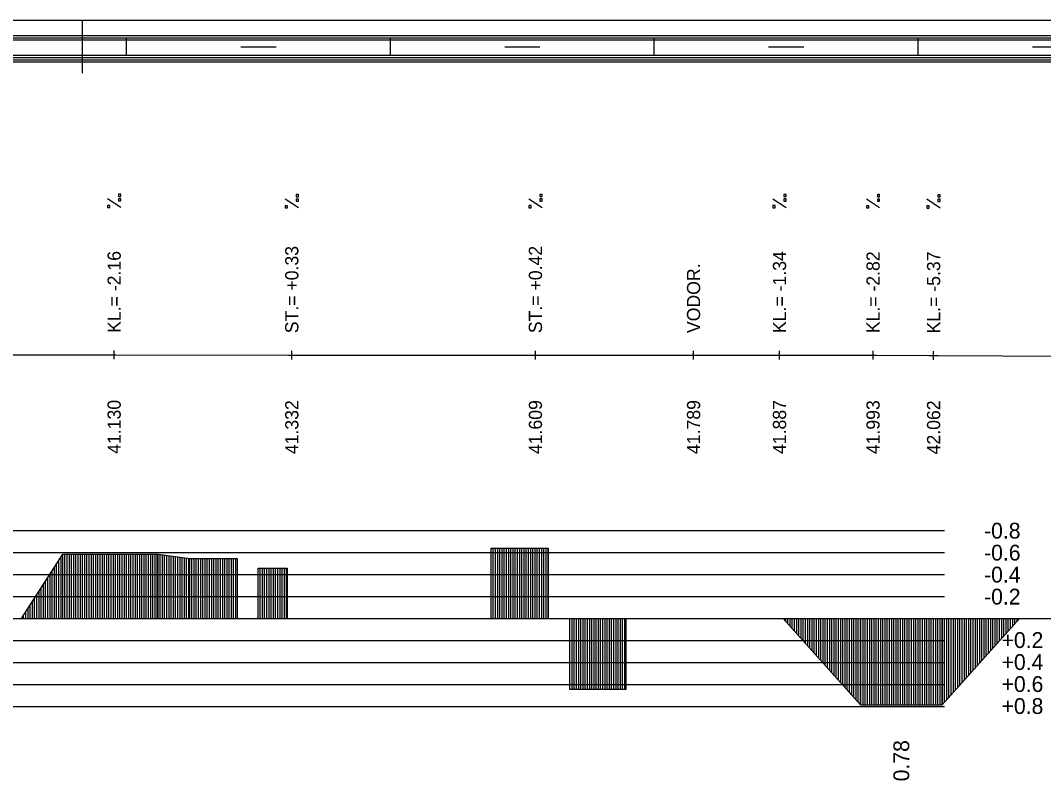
# Model space of a CAD drawing. Extents: x 2 to 10148, y 0 to 380.
# Drawn here: x 4402.9 to 4519.3, y 293.6 to 380 of the extents above; entities that cross this region are included whole.
import ezdxf

# ---------------------------------------------------------------- set-up
doc = ezdxf.new("R2010")
doc.units = 0
for name, color, linetype in [('NIVELETA_CARA', 7, 'Continuous'), ('NIVELETA_TEXT', 7, 'Continuous'), ('RAM', 7, 'Continuous'), ('ZRYCHL_CARA_C', 7, 'Continuous'), ('ZRYCHL_RASTR', 7, 'Continuous'), ('ZRYCHL_TEXT', 7, 'Continuous')]:
    doc.layers.add(name, color=color, linetype=linetype)

msp = doc.modelspace()

# ---------------------------------------------------------------- linework, layer by layer
at = {"layer": 'NIVELETA_CARA'}
for p, q in [((4386.25, 342.02), (4413.39, 341.98)), ((4413.59, 341.48), (4413.59, 342.48)), ((4433.79, 341.44), (4433.79, 342.44)), ((4461.49, 341.45), (4461.49, 342.45)), ((4479.47, 341.46), (4479.47, 342.46)), ((4489.24, 341.46), (4489.24, 342.46)), ((4499.88, 341.44), (4499.88, 342.44)), ((4506.76, 341.42), (4506.76, 342.42)), ((4413.39, 341.98), (4413.59, 341.98)), ((4413.59, 341.98), (4413.8, 341.98)), ((4413.8, 341.98), (4433.42, 341.94)), ((4433.42, 341.94), (4433.79, 341.94)), ((4433.79, 341.94), (4434.17, 341.94)), ((4434.17, 341.94), (4461.47, 341.95)), ((4461.47, 341.95), (4461.49, 341.95)), ((4461.49, 341.95), (4461.51, 341.95)), ((4461.51, 341.95), (4479.36, 341.96)), ((4479.36, 341.96), (4479.47, 341.96)), ((4479.47, 341.96), (4479.57, 341.96)), ((4479.57, 341.96), (4489.04, 341.96)), ((4489.04, 341.96), (4489.24, 341.96)), ((4489.24, 341.96), (4489.44, 341.96)), ((4489.44, 341.96), (4499.51, 341.94)), ((4499.51, 341.94), (4499.88, 341.94)), ((4499.88, 341.94), (4500.25, 341.94)), ((4500.25, 341.94), (4506.25, 341.93)), ((4506.25, 341.93), (4506.76, 341.92)), ((4506.76, 341.92), (4507.27, 341.92)), ((4507.27, 341.92), (4524.9, 341.83))]:
    msp.add_line(p, q, dxfattribs=at)
at = {"layer": 'NIVELETA_TEXT'}
for p, q in [((4414.34, 358.74), (4412.85, 359.73)), ((4414.34, 360.25), (4414.09, 360.25)), ((4414.09, 360.25), (4414.09, 360.01)), ((4414.09, 360.01), (4414.1, 360)), ((4414.09, 360), (4414.34, 360)), ((4414.34, 359.74), (4414.09, 359.74)), ((4414.09, 359.74), (4414.09, 359.5)), ((4414.09, 359.5), (4414.1, 359.49)), ((4414.09, 359.49), (4414.34, 359.49)), ((4414.34, 360), (4414.34, 360.25)), ((4414.34, 359.49), (4414.34, 359.74)), ((4434.54, 358.69), (4433.04, 359.68)), ((4434.54, 360.21), (4434.29, 360.21)), ((4434.29, 360.21), (4434.29, 359.97)), ((4434.29, 359.97), (4434.3, 359.96)), ((4434.29, 359.96), (4434.54, 359.96)), ((4434.54, 359.7), (4434.29, 359.7)), ((4434.29, 359.7), (4434.29, 359.45)), ((4434.29, 359.45), (4434.54, 359.45)), ((4434.29, 359.45), (4434.3, 359.45)), ((4434.54, 359.96), (4434.54, 360.21)), ((4434.54, 359.45), (4434.54, 359.7)), ((4462.24, 358.7), (4460.74, 359.69)), ((4462.24, 360.22), (4461.99, 360.22)), ((4461.99, 360.22), (4461.99, 359.98)), ((4461.99, 359.98), (4462, 359.97)), ((4461.99, 359.97), (4462.24, 359.97)), ((4462.24, 359.71), (4461.99, 359.71)), ((4461.99, 359.71), (4461.99, 359.46)), ((4461.99, 359.46), (4462.24, 359.46)), ((4461.99, 359.46), (4462, 359.46)), ((4462.24, 359.97), (4462.24, 360.22)), ((4462.24, 359.46), (4462.24, 359.71)), ((4489.99, 358.71), (4488.49, 359.7)), ((4489.99, 360.23), (4489.74, 360.23)), ((4489.74, 360.23), (4489.74, 359.98)), ((4489.74, 359.98), (4489.99, 359.98)), ((4489.74, 359.98), (4489.75, 359.98)), ((4489.99, 359.71), (4489.74, 359.71)), ((4489.74, 359.71), (4489.74, 359.47)), ((4489.74, 359.47), (4489.99, 359.47)), ((4489.74, 359.47), (4489.75, 359.47)), ((4489.99, 359.98), (4489.99, 360.23)), ((4489.99, 359.47), (4489.99, 359.71)), ((4500.63, 358.7), (4499.14, 359.69)), ((4500.63, 360.21), (4500.38, 360.21)), ((4500.38, 360.21), (4500.38, 359.97)), ((4500.38, 359.97), (4500.39, 359.96)), ((4500.38, 359.96), (4500.63, 359.96)), ((4500.63, 359.7), (4500.38, 359.7)), ((4500.38, 359.7), (4500.38, 359.46)), ((4500.38, 359.46), (4500.39, 359.45)), ((4500.38, 359.45), (4500.63, 359.45)), ((4500.63, 359.96), (4500.63, 360.21)), ((4500.63, 359.45), (4500.63, 359.7)), ((4507.51, 358.68), (4506.01, 359.67)), ((4507.51, 360.19), (4507.26, 360.19)), ((4507.26, 360.19), (4507.26, 359.95)), ((4507.26, 359.95), (4507.27, 359.94)), ((4507.26, 359.94), (4507.51, 359.94)), ((4507.51, 359.68), (4507.26, 359.68)), ((4507.26, 359.68), (4507.26, 359.44)), ((4507.51, 359.94), (4507.51, 360.19)), ((4507.51, 359.43), (4507.51, 359.68)), ((4413.09, 358.98), (4412.85, 358.98)), ((4412.85, 358.98), (4412.85, 358.74)), ((4412.85, 358.74), (4413.09, 358.74)), ((4412.85, 358.74), (4412.85, 358.74)), ((4413.09, 358.74), (4413.09, 358.98)), ((4433.29, 358.94), (4433.04, 358.94)), ((4433.04, 358.94), (4433.04, 358.7)), ((4433.04, 358.7), (4433.05, 358.69)), ((4433.04, 358.69), (4433.29, 358.69)), ((4433.29, 358.69), (4433.29, 358.94)), ((4460.99, 358.95), (4460.74, 358.95)), ((4460.74, 358.95), (4460.74, 358.71)), ((4460.74, 358.71), (4460.75, 358.7)), ((4460.74, 358.7), (4460.99, 358.7)), ((4460.99, 358.7), (4460.99, 358.95)), ((4488.74, 358.96), (4488.49, 358.96)), ((4488.49, 358.96), (4488.49, 358.71)), ((4488.49, 358.71), (4488.74, 358.71)), ((4488.49, 358.71), (4488.5, 358.71)), ((4488.74, 358.71), (4488.74, 358.96)), ((4499.38, 358.94), (4499.14, 358.94)), ((4499.14, 358.94), (4499.14, 358.7)), ((4499.14, 358.7), (4499.38, 358.7)), ((4499.14, 358.7), (4499.14, 358.7)), ((4499.38, 358.7), (4499.38, 358.94)), ((4506.26, 358.92), (4506.01, 358.92)), ((4506.01, 358.92), (4506.01, 358.68)), ((4506.01, 358.68), (4506.26, 358.68)), ((4506.01, 358.68), (4506.02, 358.68)), ((4506.26, 358.68), (4506.26, 358.92)), ((4507.26, 359.44), (4507.27, 359.43)), ((4507.26, 359.43), (4507.51, 359.43))]:
    msp.add_line(p, q, dxfattribs=at)
at = {"layer": 'RAM'}
for p, q in [((5128.6, 380), (4045.76, 380)), ((4410, 374), (4410, 380)), ((5128.6, 378.25), (4045.76, 378.25)), ((5128.6, 378), (4045.76, 378)), ((5128.6, 377.75), (4045.76, 377.75)), ((4415, 376), (4415, 378)), ((4428, 377), (4432, 377)), ((4445, 376), (4445, 378)), ((4458, 377), (4462, 377)), ((4475, 376), (4475, 378)), ((4488, 377), (4492, 377)), ((4505, 376), (4505, 378)), ((4518, 377), (4522, 377)), ((5128.6, 376), (4045.76, 376)), ((5128.6, 375.75), (4045.76, 375.75)), ((5128.6, 375.5), (4045.76, 375.5)), ((5128.6, 375.25), (4045.76, 375.25))]:
    msp.add_line(p, q, dxfattribs=at)
at = {"layer": 'ZRYCHL_CARA_C'}
for p, q in [((4456.45, 312), (4456.45, 320.01)), ((4456.45, 312), (4456.45, 320.01)), ((4456.45, 320.01), (4462.95, 320.01)), ((4456.7, 312), (4456.7, 320.01)), ((4456.95, 312), (4456.95, 320.01)), ((4457.2, 312), (4457.2, 320.01)), ((4457.45, 312), (4457.45, 320.01)), ((4457.7, 312), (4457.7, 320.01)), ((4457.95, 312), (4457.95, 320.01)), ((4458.2, 312), (4458.2, 320.01)), ((4458.45, 312), (4458.45, 320.01)), ((4458.7, 312), (4458.7, 320.01)), ((4458.95, 312), (4458.95, 320.01)), ((4459.2, 312), (4459.2, 320.01)), ((4459.45, 312), (4459.45, 320.01)), ((4459.7, 312), (4459.7, 320.01)), ((4459.95, 312), (4459.95, 320.01)), ((4460.2, 312), (4460.2, 320.01)), ((4460.45, 312), (4460.45, 320.01)), ((4460.7, 312), (4460.7, 320.01)), ((4460.95, 312), (4460.95, 320.01)), ((4461.2, 312), (4461.2, 320.01)), ((4461.45, 312), (4461.45, 320.01)), ((4461.7, 312), (4461.7, 320.01)), ((4461.95, 312), (4461.95, 320.01)), ((4462.2, 312), (4462.2, 320.01)), ((4462.45, 312), (4462.45, 320.01)), ((4462.7, 312), (4462.7, 320.01)), ((4462.95, 312), (4462.95, 320.01)), ((4462.95, 320.01), (4462.95, 312)), ((4403.05, 312), (4407.75, 319.32)), ((4407.55, 312), (4407.55, 319.01)), ((4407.75, 312), (4407.75, 319.32)), ((4407.75, 319.32), (4418.58, 319.32)), ((4408, 312), (4408, 319.32)), ((4408.25, 312), (4408.25, 319.32)), ((4408.5, 312), (4408.5, 319.32)), ((4408.75, 312), (4408.75, 319.32)), ((4409, 312), (4409, 319.32)), ((4409.25, 312), (4409.25, 319.32)), ((4409.5, 312), (4409.5, 319.32)), ((4409.75, 312), (4409.75, 319.32)), ((4410, 312), (4410, 319.32)), ((4410.25, 312), (4410.25, 319.32)), ((4410.5, 312), (4410.5, 319.32)), ((4410.75, 312), (4410.75, 319.32)), ((4411, 312), (4411, 319.32)), ((4411.25, 312), (4411.25, 319.32)), ((4411.5, 312), (4411.5, 319.32)), ((4411.75, 312), (4411.75, 319.32)), ((4412, 312), (4412, 319.32)), ((4412.25, 312), (4412.25, 319.32)), ((4412.5, 312), (4412.5, 319.32)), ((4412.75, 312), (4412.75, 319.32)), ((4413, 312), (4413, 319.32)), ((4413.25, 312), (4413.25, 319.32)), ((4413.5, 312), (4413.5, 319.32)), ((4413.75, 312), (4413.75, 319.32)), ((4414, 312), (4414, 319.32)), ((4414.25, 312), (4414.25, 319.32)), ((4414.5, 312), (4414.5, 319.32)), ((4414.75, 312), (4414.75, 319.32)), ((4415, 312), (4415, 319.32)), ((4415.25, 312), (4415.25, 319.32)), ((4415.5, 312), (4415.5, 319.32)), ((4415.75, 312), (4415.75, 319.32)), ((4416, 312), (4416, 319.32)), ((4416.25, 312), (4416.25, 319.32)), ((4416.5, 312), (4416.5, 319.32)), ((4416.75, 312), (4416.75, 319.32)), ((4417, 312), (4417, 319.32)), ((4417.25, 312), (4417.25, 319.32)), ((4417.5, 312), (4417.5, 319.32)), ((4417.75, 312), (4417.75, 319.32)), ((4418, 312), (4418, 319.32)), ((4418.25, 312), (4418.25, 319.32)), ((4418.5, 312), (4418.5, 319.32)), ((4418.58, 312), (4418.58, 319.32)), ((4418.58, 319.32), (4422.18, 318.84)), ((4418.83, 312), (4418.83, 319.29)), ((4419.08, 312), (4419.08, 319.26)), ((4419.33, 312), (4419.33, 319.22)), ((4419.58, 312), (4419.58, 319.19)), ((4419.83, 312), (4419.83, 319.16)), ((4420.08, 312), (4420.08, 319.12)), ((4420.33, 312), (4420.33, 319.09)), ((4420.58, 312), (4420.58, 319.05)), ((4420.83, 312), (4420.83, 319.02)), ((4421.08, 312), (4421.08, 318.99)), ((4421.33, 312), (4421.33, 318.95)), ((4421.58, 312), (4421.58, 318.92)), ((4421.83, 312), (4421.83, 318.88)), ((4422.08, 312), (4422.08, 318.85)), ((4422.18, 312), (4422.18, 318.84)), ((4422.18, 318.84), (4427.56, 318.84)), ((4422.43, 312), (4422.43, 318.84)), ((4422.68, 312), (4422.68, 318.84)), ((4422.93, 312), (4422.93, 318.84)), ((4423.18, 312), (4423.18, 318.84)), ((4423.43, 312), (4423.43, 318.84)), ((4423.68, 312), (4423.68, 318.84)), ((4423.93, 312), (4423.93, 318.84)), ((4424.18, 312), (4424.18, 318.84)), ((4424.43, 312), (4424.43, 318.84)), ((4424.68, 312), (4424.68, 318.84)), ((4424.93, 312), (4424.93, 318.84)), ((4425.18, 312), (4425.18, 318.84)), ((4425.43, 312), (4425.43, 318.84)), ((4425.68, 312), (4425.68, 318.84)), ((4425.93, 312), (4425.93, 318.84)), ((4426.18, 312), (4426.18, 318.84)), ((4426.43, 312), (4426.43, 318.84)), ((4426.68, 312), (4426.68, 318.84)), ((4426.93, 312), (4426.93, 318.84)), ((4427.18, 312), (4427.18, 318.84)), ((4427.43, 312), (4427.43, 318.84)), ((4427.56, 318.84), (4427.56, 312)), ((4406.8, 312), (4406.8, 317.84)), ((4407.05, 312), (4407.05, 318.23)), ((4407.3, 312), (4407.3, 318.62)), ((4429.95, 312), (4429.95, 317.73)), ((4429.95, 312), (4429.95, 317.73)), ((4429.95, 317.73), (4433.27, 317.73)), ((4430.2, 312), (4430.2, 317.73)), ((4430.45, 312), (4430.45, 317.73)), ((4430.7, 312), (4430.7, 317.73)), ((4430.95, 312), (4430.95, 317.73)), ((4431.2, 312), (4431.2, 317.73)), ((4431.45, 312), (4431.45, 317.73)), ((4431.7, 312), (4431.7, 317.73)), ((4431.95, 312), (4431.95, 317.73)), ((4432.2, 312), (4432.2, 317.73)), ((4432.45, 312), (4432.45, 317.73)), ((4432.7, 312), (4432.7, 317.73)), ((4432.95, 312), (4432.95, 317.73)), ((4433.2, 312), (4433.2, 317.73)), ((4433.27, 317.73), (4433.27, 312)), ((4406.05, 312), (4406.05, 316.67)), ((4406.3, 312), (4406.3, 317.06)), ((4406.55, 312), (4406.55, 317.45)), ((4405.3, 312), (4405.3, 315.51)), ((4405.55, 312), (4405.55, 315.9)), ((4405.8, 312), (4405.8, 316.29)), ((4404.55, 312), (4404.55, 314.34)), ((4404.8, 312), (4404.8, 314.73)), ((4405.05, 312), (4405.05, 315.12)), ((4403.8, 312), (4403.8, 313.17)), ((4404.05, 312), (4404.05, 313.56)), ((4404.3, 312), (4404.3, 313.95)), ((4045.76, 312), (5128.6, 312)), ((4403.3, 312), (4403.3, 312.39)), ((4403.55, 312), (4403.55, 312.78)), ((4465.37, 312), (4465.37, 303.99)), ((4465.37, 312), (4465.37, 303.99)), ((4465.62, 312), (4465.62, 303.99)), ((4465.87, 312), (4465.87, 303.99)), ((4466.12, 312), (4466.12, 303.99)), ((4466.37, 312), (4466.37, 303.99)), ((4466.62, 312), (4466.62, 303.99)), ((4466.87, 312), (4466.87, 303.99)), ((4467.12, 312), (4467.12, 303.99)), ((4467.37, 312), (4467.37, 303.99)), ((4467.62, 312), (4467.62, 303.99)), ((4467.87, 312), (4467.87, 303.99)), ((4468.12, 312), (4468.12, 303.99)), ((4468.37, 312), (4468.37, 303.99)), ((4468.62, 312), (4468.62, 303.99)), ((4468.87, 312), (4468.87, 303.99)), ((4469.12, 312), (4469.12, 303.99)), ((4469.37, 312), (4469.37, 303.99)), ((4469.62, 312), (4469.62, 303.99)), ((4469.87, 312), (4469.87, 303.99)), ((4470.12, 312), (4470.12, 303.99)), ((4470.37, 312), (4470.37, 303.99)), ((4470.62, 312), (4470.62, 303.99)), ((4470.87, 312), (4470.87, 303.99)), ((4471.12, 312), (4471.12, 303.99)), ((4471.37, 312), (4471.37, 303.99)), ((4471.62, 312), (4471.62, 303.99)), ((4471.8, 303.99), (4471.8, 312)), ((4489.66, 312), (4498.46, 302.2)), ((4489.91, 312), (4489.91, 311.72)), ((4490.16, 312), (4490.16, 311.44)), ((4490.41, 312), (4490.41, 311.16)), ((4490.66, 312), (4490.66, 310.89)), ((4490.91, 312), (4490.91, 310.61)), ((4491.16, 312), (4491.16, 310.33)), ((4491.41, 312), (4491.41, 310.05)), ((4491.66, 312), (4491.66, 309.77)), ((4491.91, 312), (4491.91, 309.49)), ((4492.16, 312), (4492.16, 309.22)), ((4492.41, 312), (4492.41, 308.94)), ((4492.66, 312), (4492.66, 308.66)), ((4492.91, 312), (4492.91, 308.38)), ((4493.16, 312), (4493.16, 308.1)), ((4493.41, 312), (4493.41, 307.82)), ((4493.66, 312), (4493.66, 307.54)), ((4493.91, 312), (4493.91, 307.27)), ((4494.16, 312), (4494.16, 306.99)), ((4494.41, 312), (4494.41, 306.71)), ((4494.66, 312), (4494.66, 306.43)), ((4494.91, 312), (4494.91, 306.15)), ((4495.16, 312), (4495.16, 305.87)), ((4495.41, 312), (4495.41, 305.59)), ((4495.66, 312), (4495.66, 305.32)), ((4495.91, 312), (4495.91, 305.04)), ((4496.16, 312), (4496.16, 304.76)), ((4496.41, 312), (4496.41, 304.48)), ((4496.66, 312), (4496.66, 304.2)), ((4496.91, 312), (4496.91, 303.92)), ((4497.16, 312), (4497.16, 303.65)), ((4497.41, 312), (4497.41, 303.37)), ((4497.66, 312), (4497.66, 303.09)), ((4497.91, 312), (4497.91, 302.81)), ((4498.16, 312), (4498.16, 302.53)), ((4498.41, 312), (4498.41, 302.25)), ((4498.46, 312), (4498.46, 302.2)), ((4498.71, 312), (4498.71, 302.2)), ((4498.96, 312), (4498.96, 302.2)), ((4499.21, 312), (4499.21, 302.2)), ((4499.46, 312), (4499.46, 302.2)), ((4499.71, 312), (4499.71, 302.2)), ((4499.96, 312), (4499.96, 302.2)), ((4500.21, 312), (4500.21, 302.2)), ((4500.46, 312), (4500.46, 302.2)), ((4500.71, 312), (4500.71, 302.2)), ((4500.96, 312), (4500.96, 302.2)), ((4501.21, 312), (4501.21, 302.2)), ((4501.46, 312), (4501.46, 302.2)), ((4501.71, 312), (4501.71, 302.2)), ((4501.96, 312), (4501.96, 302.2)), ((4502.21, 312), (4502.21, 302.2)), ((4502.46, 312), (4502.46, 302.2)), ((4502.71, 312), (4502.71, 302.2)), ((4502.96, 312), (4502.96, 302.2)), ((4503.21, 312), (4503.21, 302.2)), ((4503.46, 312), (4503.46, 302.2)), ((4503.71, 312), (4503.71, 302.2)), ((4503.96, 312), (4503.96, 302.2)), ((4504.21, 312), (4504.21, 302.2)), ((4504.46, 312), (4504.46, 302.2)), ((4504.71, 312), (4504.71, 302.2)), ((4504.96, 312), (4504.96, 302.2)), ((4505.21, 312), (4505.21, 302.2)), ((4505.46, 312), (4505.46, 302.2)), ((4505.71, 312), (4505.71, 302.2)), ((4505.96, 312), (4505.96, 302.2)), ((4506.21, 312), (4506.21, 302.2)), ((4506.46, 312), (4506.46, 302.2)), ((4506.71, 312), (4506.71, 302.2)), ((4506.96, 312), (4506.96, 302.2)), ((4507.21, 312), (4507.21, 302.2)), ((4507.46, 312), (4507.46, 302.2)), ((4507.71, 312), (4507.71, 302.2)), ((4507.72, 312), (4507.72, 302.2)), ((4507.72, 302.2), (4516.52, 312)), ((4507.97, 312), (4507.97, 302.48)), ((4508.22, 312), (4508.22, 302.75)), ((4508.47, 312), (4508.47, 303.03)), ((4508.72, 312), (4508.72, 303.31)), ((4508.97, 312), (4508.97, 303.59)), ((4509.22, 312), (4509.22, 303.87)), ((4509.47, 312), (4509.47, 304.15)), ((4509.72, 312), (4509.72, 304.43)), ((4509.97, 312), (4509.97, 304.7)), ((4510.22, 312), (4510.22, 304.98)), ((4510.47, 312), (4510.47, 305.26)), ((4510.72, 312), (4510.72, 305.54)), ((4510.97, 312), (4510.97, 305.82)), ((4511.22, 312), (4511.22, 306.1)), ((4511.47, 312), (4511.47, 306.37)), ((4511.72, 312), (4511.72, 306.65)), ((4511.97, 312), (4511.97, 306.93)), ((4512.22, 312), (4512.22, 307.21)), ((4512.47, 312), (4512.47, 307.49)), ((4512.72, 312), (4512.72, 307.77)), ((4512.97, 312), (4512.97, 308.05)), ((4513.22, 312), (4513.22, 308.32)), ((4513.47, 312), (4513.47, 308.6)), ((4513.72, 312), (4513.72, 308.88)), ((4513.97, 312), (4513.97, 309.16)), ((4514.22, 312), (4514.22, 309.44)), ((4514.47, 312), (4514.47, 309.72)), ((4514.72, 312), (4514.72, 309.99)), ((4514.97, 312), (4514.97, 310.27)), ((4515.22, 312), (4515.22, 310.55)), ((4515.47, 312), (4515.47, 310.83)), ((4515.72, 312), (4515.72, 311.11)), ((4515.97, 312), (4515.97, 311.39)), ((4516.22, 312), (4516.22, 311.67)), ((4516.47, 312), (4516.47, 311.94)), ((4465.37, 303.99), (4471.8, 303.99)), ((4498.46, 302.2), (4507.72, 302.2))]:
    msp.add_line(p, q, dxfattribs=at)
at = {"layer": 'ZRYCHL_RASTR'}
for p, q in [((4312, 322), (4508, 322)), ((4312, 319.5), (4508, 319.5)), ((4312, 317), (4508, 317)), ((4312, 314.5), (4508, 314.5)), ((4319.19, 309.5), (4508, 309.5)), ((4319.15, 307), (4508, 307)), ((4319.1, 304.5), (4508, 304.5)), ((4319.15, 302), (4508, 302))]:
    msp.add_line(p, q, dxfattribs=at)

# ---------------------------------------------------------------- texts
at = {"layer": 'NIVELETA_TEXT'}
for s, p in [('KL.= -2.16', (4414.34, 344.48)), ('ST.= +0.33', (4434.54, 344.44)), ('ST.= +0.42', (4462.24, 344.45)), ('KL.= -1.34', (4489.99, 344.46)), ('KL.= -2.82', (4500.63, 344.44)), ('KL.= -5.37', (4507.51, 344.42)), ('VODOR.', (4480.22, 344.46)), ('41.130', (4414.34, 330.73)), ('41.332', (4434.54, 330.69)), ('41.609', (4462.24, 330.7)), ('41.789', (4480.22, 330.71)), ('41.887', (4489.99, 330.71)), ('41.993', (4500.63, 330.69)), ('42.062', (4507.51, 330.67))]:
    msp.add_text(s, height=1.5, rotation=90, dxfattribs=at).set_placement(p)
at = {"layer": 'ZRYCHL_TEXT'}
for s, p in [('-0.8', (4512.5, 321.1)), ('-0.6', (4512.5, 318.6)), ('-0.4', (4512.5, 316.1)), ('-0.2', (4512.5, 313.6)), ('+0.2', (4514.49, 308.66)), ('+0.4', (4514.49, 306.16)), ('+0.6', (4514.49, 303.66)), ('+0.8', (4514.49, 301.16))]:
    msp.add_text(s, height=1.8, dxfattribs=at).set_placement(p)
msp.add_text('0.78', height=1.8, rotation=90, dxfattribs=at).set_placement((4503.99, 293.5))

doc.saveas('drawing.dxf')
